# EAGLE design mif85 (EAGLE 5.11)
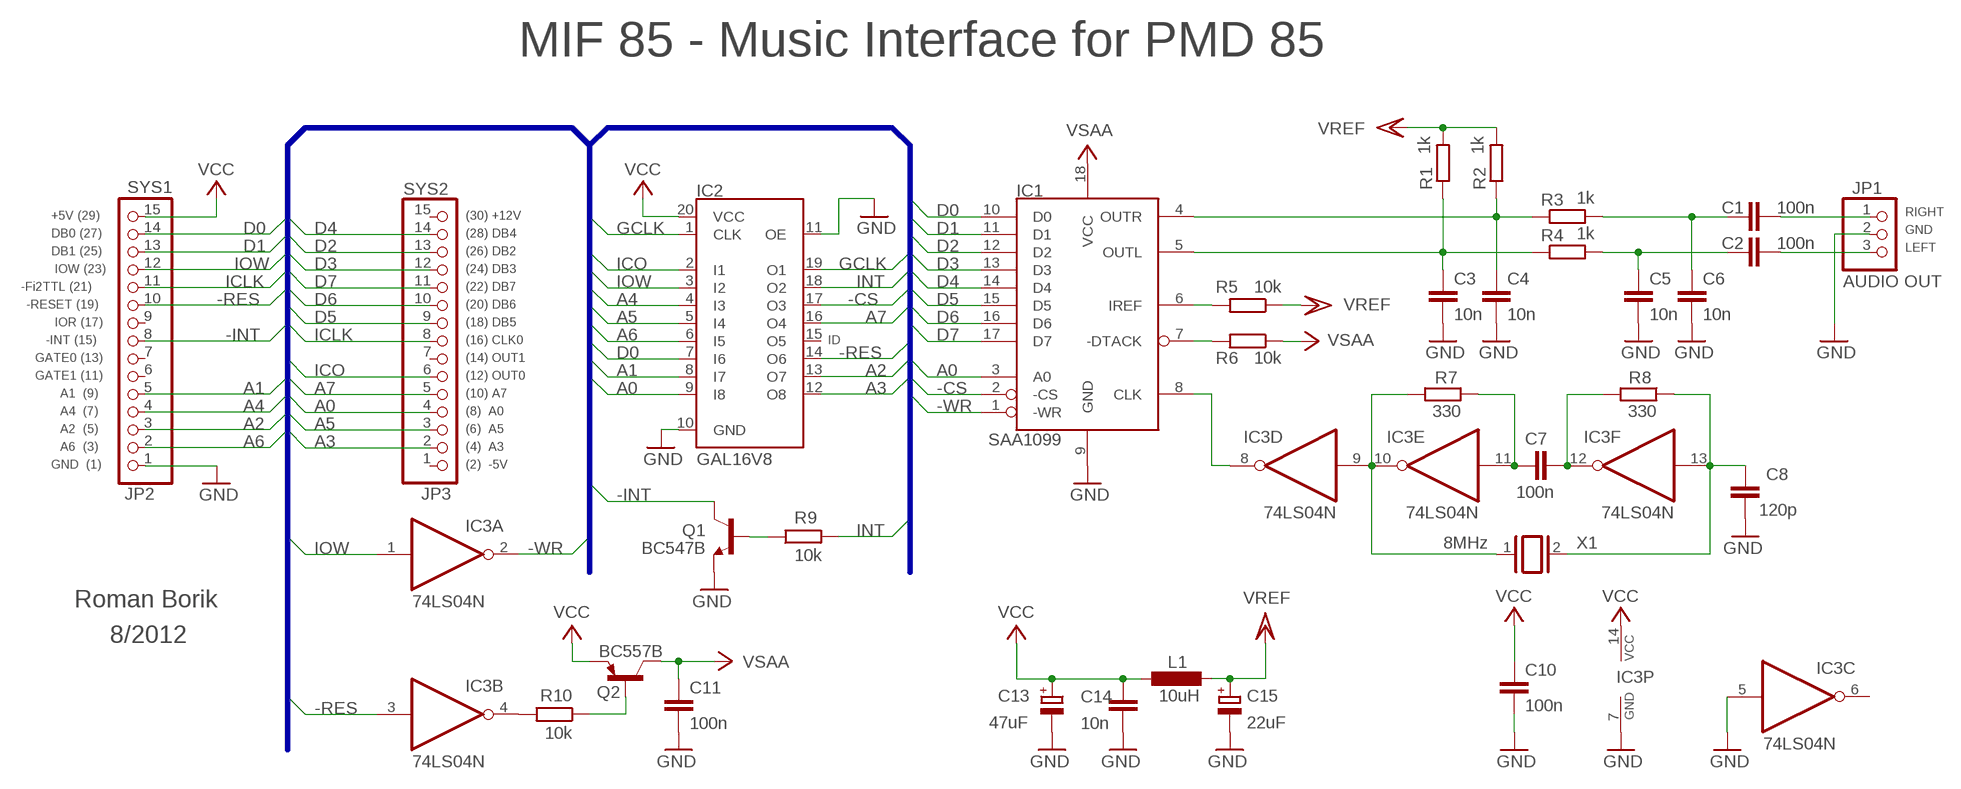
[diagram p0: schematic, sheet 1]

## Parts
C1  100n  C-EU025-025X050  [C025-025X050]
C2  100n  C-EU025-025X050  [C025-025X050]
C3  10n  C-EU025-025X050  [C025-025X050]
C4  10n  C-EU025-025X050  [C025-025X050]
C5  10n  C-EU025-025X050  [C025-025X050]
C6  10n  C-EU025-025X050  [C025-025X050]
C7  100n  C-EU025-025X050  [C025-025X050]
C8  120p  C-EU025-025X050  [C025-025X050]
C10  100n  C-EU025-025X050  [C025-025X050]
C11  100n  C-EU025-025X050  [C025-025X050]
C13  47uF  CPOL-EUE2,5-6E  [E2,5-6E]
C14  10n  C-EU025-025X050  [C025-025X050]
C15  22uF  CPOL-EUE2,5-6E  [E2,5-6E]
IC1  SAA1099  [DIL18]
IC2  GAL16V8  ATF16V8BP3  [DIL20]
IC3  74LS04N  [DIL14]
JP1  AUDIO OUT  PINHD-1X3  [1X03]
JP2  SYS1  PINHD-1X15  [1X15]
JP3  SYS2  PINHD-1X15  [1X15]
L1  10uH  L-EU0207/7  [0207/7]
Q1  BC547B  [TO92]
Q2  BC557B  BC557  [TO92]
R1  1k  R-EU_0207/7  [0207/7]
R2  1k  R-EU_0207/7  [0207/7]
R3  1k  R-EU_0207/7  [0207/7]
R4  1k  R-EU_0207/7  [0207/7]
R5  10k  R-EU_0207/7  [0207/7]
R6  10k  R-EU_0207/7  [0207/7]
R7  330  R-EU_0207/7  [0207/7]
R8  330  R-EU_0207/7  [0207/7]
R9  10k  R-EU_0207/7  [0207/7]
R10  10k  R-EU_0207/7  [0207/7]
X1  8MHz  XTAL/S  [QS]

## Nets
-CS: IC1.2(-CS) IC2.17(O3)
-INT: JP2.8 Q1.3(C)
-RES: IC2.14(O6) IC3.3(B:I) JP2.10
-WR: IC1.1(-WR) IC3.2(A:O)
A0: IC1.3(A0) IC2.9(I8) JP3.4
A1: IC2.8(I7) JP2.5
A2: IC2.13(O7) JP2.3
A3: IC2.12(O8) JP3.2
A4: IC2.4(I3) JP2.4
A5: IC2.5(I4) JP3.3
A6: IC2.6(I5) JP2.2
A7: IC2.16(O4) JP3.5
D0: IC1.10(D0) IC2.7(I6) JP2.14
D1: IC1.11(D1) JP2.13
D2: IC1.12(D2) JP3.13
D3: IC1.13(D3) JP3.12
D4: IC1.14(D4) JP3.14
D5: IC1.15(D5) JP3.9
D6: IC1.16(D6) JP3.10
D7: IC1.17(D7) JP3.11
GCLK: IC2.1(CLK) IC2.19(O1)
GND: C3.2 C4.2 C5.2 C6.2 C8.2 C10.2 C11.2 C13.- C14.2 C15.- IC1.9(GND) IC2.10(GND) IC2.11(OE) IC3.5(C:I) IC3.7(P:GND) JP1.2 JP2.1 Q1.1(E)
ICLK: JP2.11 JP3.8
ICO: IC2.2(I1) JP3.6
INT: IC2.18(O2) R9.2
IOW: IC2.3(I2) IC3.1(A:I) JP2.12
N$1: IC3.9(D:I) IC3.10(E:O) R7.2 X1.1
N$2: C7.1 IC3.12(F:O) R8.2
N$3: C7.2 IC3.11(E:I) R7.1
N$4: Q1.2(B) R9.1
N$5: C8.1 IC3.13(F:I) R8.1 X1.2
N$6: IC1.8(CLK) IC3.8(D:O)
N$8: IC3.4(B:O) R10.2
N$9: Q2.2(B) R10.1
N$10: IC1.7(-DTACK) R6.2
N$11: IC1.6(IREF) R5.2
N$12: C4.1 IC1.4(OUTR) R2.1 R3.1
N$13: C3.1 IC1.5(OUTL) R1.1 R4.1
N$14: C2.1 C5.1 R4.2
N$15: C1.1 C6.1 R3.2
N$16: C2.2 JP1.3
N$17: C1.2 JP1.1
V+: C11.1 IC1.18(VCC) Q2.3(C) R6.1 ; supply symbol labelled VSAA
VCC: C10.1 C13.+ C14.1 IC2.20(VCC) IC3.14(P:VCC) JP2.15 L1.2 Q2.1(E)
VREF: C15.+ L1.1 R1.2 R2.2 R5.1
Unconnected: IC2.15(O5) IC3.6(C:O) JP2.6 JP2.7 JP2.9 JP3.1 JP3.7 JP3.15

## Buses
SYS:D[0..7],A[0..7],IOW,-INT,-RES,ICO,ICLK,GCLK,-CS,-WR,INT

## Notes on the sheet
- MIF 85 - Music Interface for PMD 85
- RIGHT
- +5V (29) | (30) +12V
- GND
- DB0 (27) | (28) DB4
- LEFT
- DB1 (25) | (26) DB2
- IOW (23) | (24) DB3
- -Fi2TTL (21) | (22) DB7
- -RESET (19) | (20) DB6
- IOR (17) | (18) DB5
- -INT (15) | (16) CLK0 | ID
- GATE0 (13) | (14) OUT1
- GATE1 (11) | (12) OUT0
- A1  (9) | (10) A7
- A4  (7) | (8)  A0
- A2  (5) | (6)  A5
- A6  (3) | (4)  A3
- GND  (1) | (2)  -5V
- Roman Borik
- 8/2012

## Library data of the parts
C1-C8 C10 C11 C14 = rcl:C-EU: CAPACITOR, European symbol
C13 C15 = rcl:CPOL-EU: POLARIZED CAPACITOR, European symbol
IC1 = rombor:SAA1099
IC2 = atmel:ATF16V8B: High perfomance CMOS (electrically erasable) programmable logic device (PLD) ABLE-Atmel-ABEL - P18V8R, P16V8C, P16V8AS, P17V8 COPL Atmel-WinCUPL - G16V8MS, G16V8MA, G16V8AS, G16V8 LOG/IC - GAL16V8_R, GAL16V8_G7, GAL16V8_C), GAL16V8 Tango-PLD - G16V8R, G16V8C, G16V8AS, G16V8 Source: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; MPN: ATF16V8CZ-15PU; OC_FARNELL: 1551768; OC_NEWARK: 94M6254
IC3 = 74xx-eu:74*04: Hex INVERTER
JP1 = pinhead:PINHD-1X3: PIN HEADER
JP2 JP3 = pinhead:PINHD-1X15: PIN HEADER
L1 = rcl:L-EU: INDUCTOR, European symbol
Q1 = transistor-npn:BC547*: NPN Transistor
Q2 = transistor-pnp:BC557: PNP Transistor
R1-R10 = rcl:R-EU_: RESISTOR, European symbol
X1 = special:XTAL/S: CRYSTAL

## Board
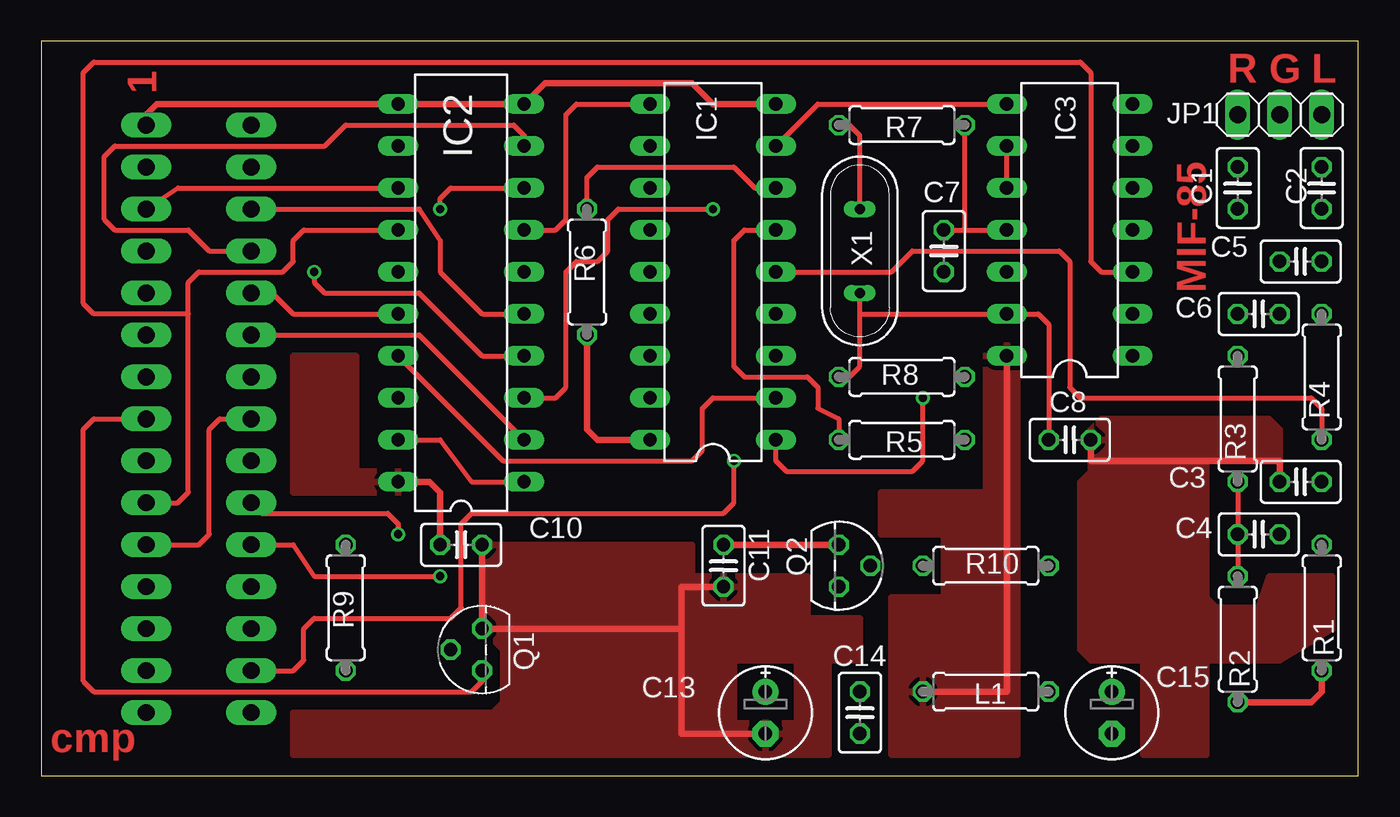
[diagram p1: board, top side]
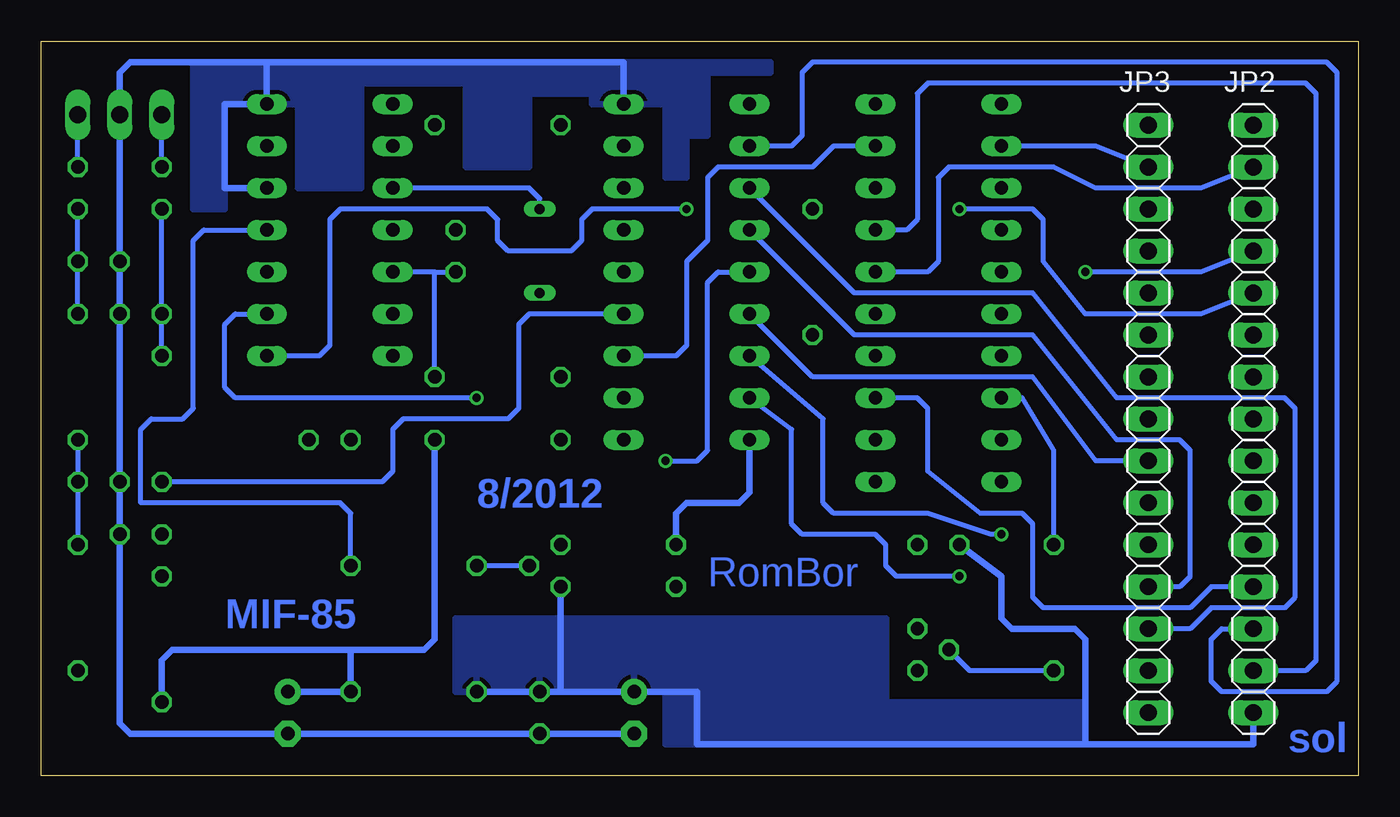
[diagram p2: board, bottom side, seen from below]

Size 79.68 x 44.44 mm. Coordinates in mm from the lower left corner, seen from the top.
Outline: 0,0 79.68,0 79.68,44.44 0,44.44 0,0
Copper layers (1*16): Top 0.0356mm / dielectric 1.5011mm / Bottom 0.0356mm
Design rules "LaenPCBOrder": minimum track width 6mil, minimum drill 13mil, track to track 6mil, track to pad 6mil, pad to pad 6mil, via to via 6mil, smd to smd 6mil, copper to edge 15mil, drill to drill 6mil, minimum pad ring 7mil, minimum via ring 7mil, stop-mask expansion 4mil, vias tented up to drill 0mil, thermal gap 10mil

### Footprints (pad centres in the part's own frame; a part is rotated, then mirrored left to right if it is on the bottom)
C025-025X050 = drill 0.813 octagon: 1 -1.27,0; 2 1.27,0
E2,5-6E = drill 0.813 pad 1.575 round: + -1.27,0 | drill 0.813 pad 1.575 octagon: - 1.27,0
DIL18 = drill 0.813 long: 1 -10.16,-3.81; 2 -7.62,-3.81; 3 -5.08,-3.81; 4 -2.54,-3.81; 5 0,-3.81; 6 2.54,-3.81; 7 5.08,-3.81; 8 7.62,-3.81; 9 10.16,-3.81; 10 10.16,3.81; 11 7.62,3.81; 12 5.08,3.81; 13 2.54,3.81; 14 0,3.81; 15 -2.54,3.81; 16 -5.08,3.81; 17 -7.62,3.81; 18 -10.16,3.81
DIL20 = drill 0.813 long: 1 -11.43,-3.81; 2 -8.89,-3.81; 3 -6.35,-3.81; 4 -3.81,-3.81; 5 -1.27,-3.81; 6 1.27,-3.81; 7 3.81,-3.81; 8 6.35,-3.81; 9 8.89,-3.81; 10 11.43,-3.81; 11 11.43,3.81; 12 8.89,3.81; 13 6.35,3.81; 14 3.81,3.81; 15 1.27,3.81; 16 -1.27,3.81; 17 -3.81,3.81; 18 -6.35,3.81; 19 -8.89,3.81; 20 -11.43,3.81
DIL14 = drill 0.813 long: 1 -7.62,-3.81; 2 -5.08,-3.81; 3 -2.54,-3.81; 4 0,-3.81; 5 2.54,-3.81; 6 5.08,-3.81; 7 7.62,-3.81; 8 7.62,3.81; 9 5.08,3.81; 10 2.54,3.81; 11 0,3.81; 12 -2.54,3.81; 13 -5.08,3.81; 14 -7.62,3.81
1X03 = drill 1.016 long: 1 -2.54,0; 2 0,0; 3 2.54,0
1X15 = drill 1.016 long: 1 -17.78,0; 2 -15.24,0; 3 -12.7,0; 4 -10.16,0; 5 -7.62,0; 6 -5.08,0; 7 -2.54,0; 8 0,0; 9 2.54,0; 10 5.08,0; 11 7.62,0; 12 10.16,0; 13 12.7,0; 14 15.24,0; 15 17.78,0
0207/7 = drill 0.813 octagon: 1 -3.81,0; 2 3.81,0
TO92 = drill 0.813 octagon: 1 1.27,0; 2 0,1.905; 3 -1.27,0
QS = drill 0.61 long: 1 -2.54,0; 2 2.54,0

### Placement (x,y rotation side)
C1  72.39,35.56 90 top
C2  77.47,35.56 90 top
C3  76.2,17.78 180 top
C4  73.66,14.61 0 top
C5  76.2,31.11 180 top
C6  73.66,27.94 0 top
C7  54.61,31.75 90 top
C8  62.23,20.32 0 top
C10  25.4,13.97 0 top
C11  41.27,12.7 270 top
C13  43.81,3.81 270 top
C14  49.53,3.81 270 top
C15  64.77,3.81 270 top
IC1  40.64,30.48 90 top
IC2  25.4,29.21 90 top
IC3  62.23,33.02 90 top
JP1  74.93,40.01 0 top
JP2  6.35,21.59 270 bottom
JP3  12.7,21.59 270 bottom
L1  57.15,5.08 180 top
Q1  26.67,7.62 90 top
Q2  48.26,12.7 270 top
R1  77.47,10.16 270 top
R2  72.39,8.26 270 top
R3  72.39,21.59 90 top
R4  77.47,24.13 90 top
R5  52.07,20.32 180 top
R6  33.02,30.48 90 top
R7  52.07,39.37 180 top
R8  52.07,24.13 0 top
R9  18.41,10.16 90 top
R10  57.15,12.7 0 top
X1  49.53,31.75 270 top

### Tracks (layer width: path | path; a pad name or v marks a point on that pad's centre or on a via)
-CS
  Top 0.305: IC2.17 27.94,19.05 39.37,19.05 40.01,19.68 40.01,22.23 40.64,22.86 IC1.2
-INT
  Top 0.305: Q1.3 26.67,5.71 26.04,5.08 3.17,5.08 2.54,5.71 2.54,20.95 3.17,21.59 JP2.8
-RES
  Top 0.305: IC2.14 15.88,33.02 15.24,32.38 15.24,31.11 14.61,30.48 9.53,30.48 8.89,29.84 8.89,27.94 | 8.89,27.94 8.89,17.14 8.26,16.51 JP2.10 | IC3.3 64.14,30.48 63.5,31.11 63.5,42.55 62.87,43.18 3.17,43.18 2.54,42.55 2.54,28.57 3.17,27.94 8.89,27.94
-WR  (via drill 0.5)
  Top 0.305: IC1.1 44.45,19.05 45.09,18.41 52.7,18.41 53.34,19.05 v53.34,22.86
  Bottom 0.305: v53.34,22.86 67.94,22.86 68.58,23.5 68.58,27.3 67.94,27.94 IC3.2
A0
  Top 0.305: JP3.4 10.16,31.75 8.89,33.02 4.45,33.02 3.81,33.66 3.81,37.47 4.45,38.1 17.14,38.1 18.41,39.37 28.57,39.37 29.21,38.73 IC2.9
  Bottom 0.305: IC2.9 31.75,38.1 33.02,36.83 38.73,36.83 39.37,36.2 39.37,32.38 40.64,31.11 40.64,26.04 41.27,25.4 IC1.3
A1  (via drill 0.5)
  Top 0.305: v24.13,34.29 24.13,34.92 24.77,35.56 IC2.8
  Bottom 0.305: v24.13,34.29 19.68,34.29 19.05,33.66 19.05,31.11 16.51,27.94 9.53,27.94 JP2.5
A2
  Top 0.305: IC2.13 8.26,35.56 JP2.3
A3
  Bottom 0.305: IC2.12 15.88,38.1 JP3.2
A4  (via drill 0.5)
  Top 0.305: IC2.4 26.67,25.4 22.86,29.21 17.14,29.21 16.51,29.84 v16.51,30.48
  Bottom 0.305: v16.51,30.48 9.53,30.48 JP2.4
A5
  Top 0.305: IC2.5 26.67,27.94 24.13,30.48 24.13,32.38 22.86,34.29 JP3.3
A6
  Bottom 0.305: IC2.6 26.04,30.48 25.4,31.11 25.4,36.2 24.77,36.83 18.41,36.83 15.88,35.56 9.53,35.56 JP2.2
A7
  Top 0.305: IC2.16 15.24,27.94 13.97,29.21 JP3.5
D0
  Top 0.305: IC2.7 31.11,33.02 31.75,33.66 31.75,40.01 32.38,40.64 IC1.10
  Bottom 0.305: JP2.14 3.17,6.35 2.54,6.99 2.54,41.27 3.17,41.91 26.04,41.91 26.67,41.27 26.67,33.66 27.3,33.02 IC2.7
D1
  Bottom 0.305: IC1.11 34.29,38.1 33.66,38.73 33.66,42.55 33.02,43.18 1.91,43.18 1.27,42.55 1.27,5.71 1.91,5.08 8.26,5.08 8.89,5.71 8.89,8.26 8.26,8.89 JP2.13
D2
  Bottom 0.305: IC1.12 30.48,29.21 19.68,29.21 14.61,22.86 4.45,22.86 3.81,22.23 3.81,10.79 4.45,10.16 8.89,10.16 10.16,8.89 JP3.13
D3
  Bottom 0.305: IC1.13 30.48,26.67 19.68,26.67 14.61,20.32 10.79,20.32 10.16,19.68 10.16,12.06 10.79,11.43 JP3.12
D4  (via drill 0.5)
  Top 0.305: v41.91,19.05 41.91,16.51 41.27,15.88 26.04,15.88 25.4,15.24 25.4,10.16 24.77,9.53 16.51,9.53 15.88,8.89 15.88,6.99 15.24,6.35 JP3.14
  Bottom 0.305: IC1.14 38.73,30.48 39.37,29.84 39.37,19.68 40.01,19.05 v41.91,19.05
D5
  Bottom 0.305: IC1.15 33.02,24.13 19.68,24.13 15.88,19.05 JP3.9
D6  (via drill 0.5)
  Top 0.305: v21.59,14.61 21.59,15.24 20.95,15.88 13.34,15.88 JP3.10
  Bottom 0.305: v21.59,14.61 22.23,14.61 26.04,15.88 31.75,15.88 32.38,16.51 32.38,21.59 IC1.16
D7  (via drill 0.5)
  Top 0.305: v24.13,12.06 16.51,12.06 15.24,13.97 JP3.11
  Bottom 0.305: IC1.17 34.29,20.95 34.29,15.24 33.66,14.61 29.21,14.61 28.57,13.97 28.57,12.7 27.94,12.06 v24.13,12.06
GCLK
  Top 0.305: IC2.19 24.13,20.32 26.04,17.78 IC2.1
GND
  Top 0.406: IC1.9 40.64,40.64 39.37,41.91 30.48,41.91 IC2.10 IC2.11 6.99,40.64 6.35,40.01 JP2.1 | C10.2 Q1.1 38.73,8.89 | C8.2 63.5,19.05 74.93,19.05 C3.2 | 38.73,8.89 38.73,11.43 C11.2 | C13.- 38.73,2.54 38.73,8.89
  Bottom 0.406: C13.- C14.2 C15.- 74.3,2.54 74.93,3.17 C4.2 C3.2 C6.2 C5.2 JP1.2 74.93,42.55 74.3,43.18 66.04,43.18 | IC1.9 44.45,43.18 66.04,43.18 | 66.04,43.18 IC3.7 68.58,40.64 68.58,35.56 IC3.5
  pour Top: 26.67,13.97 39.37,13.97 39.37,12.06 46.35,12.06 46.35,9.53 41.91,9.53 41.91,1.27 15.24,1.27 15.24,3.81 27.3,3.81 27.94,4.45 27.94,7.62 26.67,8.89
  pour Top: 41.91,9.53 49.53,9.53 49.53,6.99 47.62,6.99 47.62,1.27 41.91,1.27 41.91,3.17 45.72,3.17 45.72,6.99 41.91,6.99
  pour Top: 63.5,20.95 63.5,18.41 62.87,17.78 62.87,7.62 63.5,6.99 66.67,6.99 66.67,1.27 70.48,1.27 70.48,6.99 74.93,6.99 78.11,8.89 78.11,12.06 74.3,12.06 73.66,10.16 71.12,10.16 70.48,10.79 70.48,19.05 74.93,19.05 74.93,20.95 74.3,21.59 64.14,21.59
  pour Bottom: 70.48,43.18 35.56,43.18 35.56,42.55 39.37,42.55 39.37,38.73 40.64,38.73 40.64,36.2 41.91,36.2 41.91,40.64 46.35,40.64 46.35,41.27 50.16,41.27 50.16,36.83 53.98,36.83 53.98,41.91 60.33,41.91 60.33,35.56 64.14,35.56 64.14,40.64 68.58,40.64 68.58,34.29 70.48,34.29
ICLK
  Top 0.305: JP2.11 9.53,13.97 10.16,14.61 10.16,20.95 10.79,21.59 JP3.8
ICO
  Top 0.305: IC2.2 22.86,26.67 JP3.6
INT
  Bottom 0.305: R9.2 18.41,19.68 20.32,22.86 IC2.18
IOW  (via drill 0.5)
  Top 0.305: v40.64,34.29 34.92,34.29 34.29,33.66 34.29,31.75 33.66,31.11 32.38,31.11 31.75,30.48 31.75,23.5 31.11,22.86 IC2.3
  Bottom 0.305: IC2.3 26.67,22.86 26.04,22.23 26.04,18.41 22.86,15.88 20.32,15.88 19.68,15.24 19.68,10.79 19.05,10.16 10.16,10.16 8.89,11.43 JP2.12 | IC3.1 62.87,25.4 62.23,26.04 62.23,33.66 61.59,34.29 52.7,34.29 52.07,33.66 52.07,32.38 51.44,31.75 47.62,31.75 46.99,32.38 46.99,33.66 46.35,34.29 v40.64,34.29
N$1
  Top 0.305: IC3.10 IC3.9 | X1.1 49.53,38.73 48.9,39.37 R7.2
  Bottom 0.305: IC3.10 50.16,35.56 49.53,34.92 X1.1
N$2
  Bottom 0.305: R8.2 55.88,30.48 | 55.88,30.48 C7.1 | 55.88,30.48 IC3.12
N$3
  Top 0.305: 55.88,33.02 IC3.11 | C7.2 55.88,33.02 | 55.88,33.02 R7.1
N$4
  Bottom 0.305: R9.1 23.5,6.35 Q1.2
N$5
  Top 0.305: 49.53,27.94 IC3.13 60.33,27.94 60.96,27.3 C8.1 | R8.1 48.9,24.13 49.53,24.77 49.53,27.94 | 49.53,27.94 X1.2
N$6
  Top 0.305: IC1.8 46.99,40.64 IC3.8
N$8
  Bottom 0.305: R10.2 60.96,15.88 61.59,16.51 73.66,16.51 73.66,20.95 73.03,21.59 71.12,21.59 70.48,22.23 70.48,32.38 69.85,33.02 IC3.4
N$9
  Bottom 0.305: Q2.2 R10.1
N$10
  Top 0.305: R6.2 33.02,36.2 33.66,36.83 41.91,36.83 43.18,35.56 IC1.7
N$11
  Top 0.305: R5.2 48.26,21.59 46.99,22.23 46.99,23.5 46.35,24.13 42.55,24.13 41.91,24.77 41.91,32.38 42.55,33.02 IC1.6
N$12
  Top 0.305: R2.1 C4.1 R3.1
  Bottom 0.305: IC1.4 50.16,27.94 50.8,27.3 50.8,22.23 51.44,21.59 57.78,21.59 58.42,20.95 58.42,18.41 59.05,17.78 R3.1
N$13
  Top 0.305: IC1.5 51.44,30.48 52.7,31.75 61.59,31.75 62.23,31.11 62.23,23.5 62.87,22.86 76.83,22.86 77.47,22.23 R4.1
  Bottom 0.305: R1.1 C3.1 R4.1
N$14
  Bottom 0.305: C2.1 C5.1 R4.2
N$15
  Bottom 0.305: C1.1 C6.1 R3.2
N$16
  Bottom 0.305: C2.2 JP1.3
N$17
  Bottom 0.305: C1.2 JP1.1
V+
  Top 0.406: C11.1 Q2.3 | IC1.18 33.66,20.32 33.02,20.95 R6.1
  Bottom 0.406: IC1.18 36.83,17.14 37.47,16.51 40.64,16.51 41.27,15.88 C11.1
VCC
  Top 0.406: C10.1 24.13,17.14 23.5,17.78 IC2.20 | L1.2 58.42,5.08 IC3.14
  Bottom 0.406: JP2.15 6.35,1.91 40.01,1.91 40.01,5.08 C13.+ 48.26,5.08 | 16.51,1.91 16.51,8.26 17.14,8.89 20.95,8.89 21.59,9.53 21.59,12.06 C10.1 | L1.2 C14.1 48.26,5.08 | 48.26,5.08 Q2.1
  pour Top: 51.44,1.27 59.05,1.27 59.05,26.04 57.15,26.04 57.15,17.14 50.8,17.14 50.8,14.61 54.61,14.61 54.61,10.79 51.44,10.79
  pour Top: 15.24,25.4 19.05,25.4 19.05,18.41 22.86,18.41 22.86,17.14 15.24,17.14
  pour Bottom: 16.51,4.45 28.57,4.45 28.57,9.53 54.61,9.53 54.61,5.08 41.91,5.08 41.91,1.91 16.51,1.91
VREF
  Top 0.406: R1.2 77.47,5.08 76.83,4.45 R2.2
  Bottom 0.406: C15.+ L1.1 60.96,7.62 | R5.1 55.88,8.26 56.52,7.62 60.96,7.62 | 60.96,7.62 71.75,7.62 72.39,6.99 R2.2

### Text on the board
Top: R | G | L | 1 | MIF-85 | cmp
Bottom: 8/2012 | RomBor | MIF-85 | sol
Document: JP2 a JP3 sa osadzuju na stranu spojov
